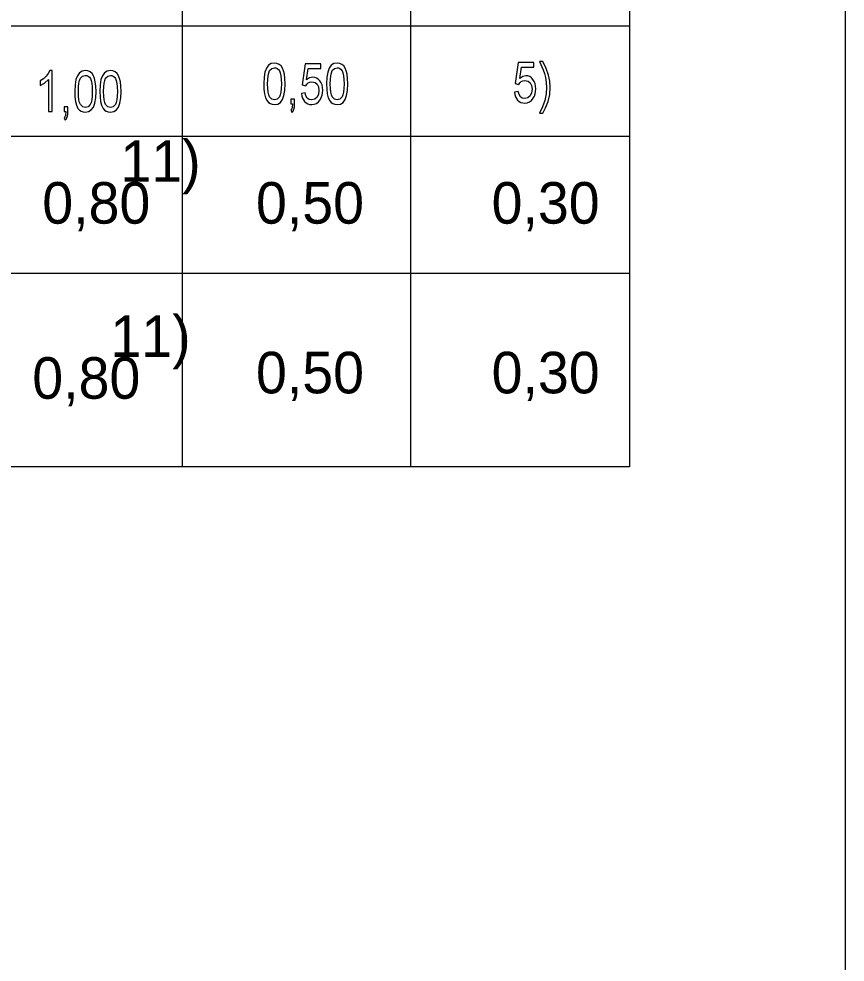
# Model space of a CAD drawing. Extents: x -480568.5 to -480543.1, y -1126945.4 to -1126930.6.
# Drawn here: x -480545.02 to -480543.093, y -1126940.968 to -1126938.768 of the extents above; entities that cross this region are included whole.
import ezdxf

# ---------------------------------------------------------------- set-up
doc = ezdxf.new("R2010")
doc.units = 0
doc.layers.add('detaily', color=7, linetype='Continuous')
doc.layers.add('EL1', color=7, linetype='Continuous')

msp = doc.modelspace()

# ---------------------------------------------------------------- linework, layer by layer
at = {"layer": 'detaily'}
msp.add_line((-480543.0929, -1126930.5663), (-480543.0929, -1126945.4163), dxfattribs=at)
msp.add_lwpolyline([(-480543.5956, -1126939.8124), (-480551.8459, -1126939.8124), (-480551.8459, -1126936.5789), (-480543.5956, -1126936.5789)], close=True, dxfattribs=at)
at = {"layer": 'EL1'}
for p, q in [((-480544.6383, -1126939.8121), (-480544.6383, -1126936.5789)), ((-480544.1063, -1126936.5789), (-480544.1063, -1126939.8121)), ((-480550.8351, -1126938.7844), (-480543.5956, -1126938.7844)), ((-480543.5956, -1126939.0426), (-480551.8459, -1126939.0426)), ((-480543.5956, -1126939.3618), (-480551.8459, -1126939.3618))]:
    msp.add_line(p, q, dxfattribs=at)
for points in [[(-480544.4489, -1126938.9195), (-480544.4484, -1126938.932), (-480544.447, -1126938.9427), (-480544.4446, -1126938.9518), (-480544.4413, -1126938.959), (-480544.4379, -1126938.9629), (-480544.4339, -1126938.9657), (-480544.4292, -1126938.9673), (-480544.424, -1126938.9679), (-480544.4164, -1126938.9666), (-480544.4102, -1126938.9628), (-480544.4054, -1126938.9563), (-480544.4019, -1126938.9469), (-480544.3999, -1126938.9347), (-480544.3992, -1126938.9195), (-480544.3996, -1126938.9069), (-480544.4009, -1126938.8971), (-480544.4028, -1126938.8894), (-480544.4052, -1126938.883), (-480544.4085, -1126938.8779), (-480544.4129, -1126938.8742), (-480544.4182, -1126938.8718), (-480544.424, -1126938.8711), (-480544.4316, -1126938.8724), (-480544.4378, -1126938.8762), (-480544.4426, -1126938.8827), (-480544.4461, -1126938.892), (-480544.4482, -1126938.9042)], [(-480544.3611, -1126938.9423), (-480544.3603, -1126938.9479), (-480544.3588, -1126938.9528), (-480544.3566, -1126938.9571), (-480544.3537, -1126938.9609), (-480544.3503, -1126938.964), (-480544.3463, -1126938.9661), (-480544.3419, -1126938.9675), (-480544.337, -1126938.9679), (-480544.3311, -1126938.9672), (-480544.3259, -1126938.965), (-480544.3213, -1126938.9615), (-480544.3173, -1126938.9565), (-480544.3148, -1126938.9516), (-480544.3129, -1126938.9463), (-480544.3118, -1126938.9406), (-480544.3114, -1126938.9344), (-480544.3118, -1126938.9281), (-480544.3131, -1126938.9222), (-480544.3152, -1126938.9171), (-480544.3182, -1126938.9125), (-480544.3218, -1126938.9088), (-480544.3257, -1126938.9061), (-480544.33, -1126938.9045), (-480544.3347, -1126938.904), (-480544.342, -1126938.9055), (-480544.3489, -1126938.9103), (-480544.3451, -1126938.8839), (-480544.3158, -1126938.8839), (-480544.3158, -1126938.8729), (-480544.3523, -1126938.8729), (-480544.3596, -1126938.9222), (-480544.3509, -1126938.924), (-480544.3485, -1126938.9204), (-480544.3454, -1126938.9175), (-480544.3416, -1126938.9156), (-480544.3367, -1126938.9149), (-480544.3294, -1126938.9163), (-480544.3242, -1126938.9203), (-480544.3212, -1126938.9268), (-480544.3202, -1126938.9351), (-480544.3213, -1126938.944), (-480544.3245, -1126938.951), (-480544.3298, -1126938.9555), (-480544.337, -1126938.9569), (-480544.3429, -1126938.9559), (-480544.3474, -1126938.9528), (-480544.3505, -1126938.9477), (-480544.3523, -1126938.9405)], [(-480544.3026, -1126938.9195), (-480544.3021, -1126938.932), (-480544.3007, -1126938.9427), (-480544.2984, -1126938.9518), (-480544.295, -1126938.959), (-480544.2916, -1126938.9629), (-480544.2876, -1126938.9657), (-480544.283, -1126938.9673), (-480544.2777, -1126938.9679), (-480544.2701, -1126938.9666), (-480544.2639, -1126938.9628), (-480544.2591, -1126938.9563), (-480544.2557, -1126938.9469), (-480544.2536, -1126938.9347), (-480544.2529, -1126938.9195), (-480544.2533, -1126938.9069), (-480544.2546, -1126938.8971), (-480544.2566, -1126938.8894), (-480544.259, -1126938.883), (-480544.2622, -1126938.8779), (-480544.2666, -1126938.8742), (-480544.2719, -1126938.8718), (-480544.2777, -1126938.8711), (-480544.2853, -1126938.8724), (-480544.2915, -1126938.8762), (-480544.2963, -1126938.8827), (-480544.2998, -1126938.892), (-480544.3019, -1126938.9042)], [(-480543.8641, -1126938.939), (-480543.8633, -1126938.9446), (-480543.8619, -1126938.9495), (-480543.8597, -1126938.9539), (-480543.8568, -1126938.9576), (-480543.8533, -1126938.9607), (-480543.8494, -1126938.9629), (-480543.845, -1126938.9642), (-480543.8401, -1126938.9646), (-480543.8342, -1126938.9639), (-480543.8289, -1126938.9618), (-480543.8243, -1126938.9582), (-480543.8204, -1126938.9532), (-480543.8178, -1126938.9483), (-480543.8159, -1126938.943), (-480543.8148, -1126938.9373), (-480543.8144, -1126938.9311), (-480543.8149, -1126938.9248), (-480543.8161, -1126938.919), (-480543.8183, -1126938.9138), (-480543.8212, -1126938.9092), (-480543.8248, -1126938.9055), (-480543.8287, -1126938.9028), (-480543.8331, -1126938.9012), (-480543.8378, -1126938.9007), (-480543.845, -1126938.9023), (-480543.8519, -1126938.907), (-480543.8481, -1126938.8806), (-480543.8188, -1126938.8806), (-480543.8188, -1126938.8696), (-480543.8554, -1126938.8696), (-480543.8627, -1126938.9189), (-480543.8539, -1126938.9208), (-480543.8515, -1126938.9171), (-480543.8485, -1126938.9142), (-480543.8446, -1126938.9123), (-480543.8398, -1126938.9116), (-480543.8324, -1126938.913), (-480543.8273, -1126938.9171), (-480543.8242, -1126938.9235), (-480543.8232, -1126938.9318), (-480543.8243, -1126938.9407), (-480543.8276, -1126938.9477), (-480543.8329, -1126938.9522), (-480543.84, -1126938.9537), (-480543.846, -1126938.9526), (-480543.8504, -1126938.9495), (-480543.8536, -1126938.9444), (-480543.8554, -1126938.9372)], [(-480543.7983, -1126938.9883), (-480543.7915, -1126938.9756), (-480543.7859, -1126938.9608), (-480543.782, -1126938.9447), (-480543.7808, -1126938.928), (-480543.7817, -1126938.9134), (-480543.7846, -1126938.8994), (-480543.7902, -1126938.8836), (-480543.7983, -1126938.8678), (-480543.8056, -1126938.8678), (-480543.797, -1126938.8866), (-480543.794, -1126938.8955), (-480543.7918, -1126938.9047), (-480543.7901, -1126938.9163), (-480543.7895, -1126938.9281), (-480543.7905, -1126938.9432), (-480543.7936, -1126938.9582), (-480543.7986, -1126938.9733), (-480543.8056, -1126938.9883)], [(-480544.9426, -1126938.9838), (-480544.9426, -1126938.8888), (-480544.9482, -1126938.8888), (-480544.9515, -1126938.8951), (-480544.9566, -1126938.9015), (-480544.963, -1126938.9075), (-480544.9703, -1126938.9126), (-480544.9703, -1126938.9238), (-480544.9603, -1126938.9178), (-480544.9513, -1126938.9098), (-480544.9513, -1126938.9838)], [(-480544.8899, -1126938.9373), (-480544.8894, -1126938.9498), (-480544.888, -1126938.9605), (-480544.8857, -1126938.9696), (-480544.8824, -1126938.9768), (-480544.879, -1126938.9807), (-480544.8749, -1126938.9835), (-480544.8703, -1126938.9851), (-480544.865, -1126938.9857), (-480544.8574, -1126938.9844), (-480544.8512, -1126938.9805), (-480544.8464, -1126938.974), (-480544.843, -1126938.9647), (-480544.8409, -1126938.9525), (-480544.8402, -1126938.9373), (-480544.8406, -1126938.9246), (-480544.8419, -1126938.9149), (-480544.8439, -1126938.9072), (-480544.8463, -1126938.9008), (-480544.8495, -1126938.8957), (-480544.8539, -1126938.8919), (-480544.8592, -1126938.8896), (-480544.865, -1126938.8888), (-480544.8726, -1126938.8901), (-480544.8788, -1126938.894), (-480544.8837, -1126938.9005), (-480544.8871, -1126938.9098), (-480544.8892, -1126938.922)], [(-480544.8811, -1126938.9373), (-480544.8808, -1126938.9269), (-480544.88, -1126938.9183), (-480544.8785, -1126938.9115), (-480544.8764, -1126938.9064), (-480544.8714, -1126938.9015), (-480544.8652, -1126938.8998), (-480544.8617, -1126938.9003), (-480544.8586, -1126938.9017), (-480544.8558, -1126938.904), (-480544.8534, -1126938.9072), (-480544.8515, -1126938.9119), (-480544.8501, -1126938.9185), (-480544.8493, -1126938.9269), (-480544.849, -1126938.9373), (-480544.8493, -1126938.948), (-480544.8501, -1126938.9566), (-480544.8516, -1126938.9632), (-480544.8536, -1126938.9677), (-480544.8588, -1126938.973), (-480544.865, -1126938.9747), (-480544.8713, -1126938.973), (-480544.8765, -1126938.9677), (-480544.8785, -1126938.9632), (-480544.88, -1126938.9566), (-480544.8808, -1126938.948)], [(-480544.8314, -1126938.9373), (-480544.8309, -1126938.9498), (-480544.8295, -1126938.9605), (-480544.8271, -1126938.9696), (-480544.8238, -1126938.9768), (-480544.8204, -1126938.9807), (-480544.8164, -1126938.9835), (-480544.8117, -1126938.9851), (-480544.8065, -1126938.9857), (-480544.7989, -1126938.9844), (-480544.7927, -1126938.9805), (-480544.7879, -1126938.974), (-480544.7844, -1126938.9647), (-480544.7824, -1126938.9525), (-480544.7817, -1126938.9373), (-480544.7821, -1126938.9246), (-480544.7834, -1126938.9149), (-480544.7853, -1126938.9072), (-480544.7877, -1126938.9008), (-480544.791, -1126938.8957), (-480544.7954, -1126938.8919), (-480544.8007, -1126938.8896), (-480544.8065, -1126938.8888), (-480544.8141, -1126938.8901), (-480544.8203, -1126938.894), (-480544.8251, -1126938.9005), (-480544.8286, -1126938.9098), (-480544.8307, -1126938.922)], [(-480544.8226, -1126938.9373), (-480544.8223, -1126938.9269), (-480544.8214, -1126938.9183), (-480544.8199, -1126938.9115), (-480544.8179, -1126938.9064), (-480544.8128, -1126938.9015), (-480544.8066, -1126938.8998), (-480544.8032, -1126938.9003), (-480544.8001, -1126938.9017), (-480544.7973, -1126938.904), (-480544.7949, -1126938.9072), (-480544.793, -1126938.9119), (-480544.7916, -1126938.9185), (-480544.7907, -1126938.9269), (-480544.7904, -1126938.9373), (-480544.7907, -1126938.948), (-480544.7916, -1126938.9566), (-480544.7931, -1126938.9632), (-480544.7951, -1126938.9677), (-480544.8003, -1126938.973), (-480544.8065, -1126938.9747), (-480544.8128, -1126938.973), (-480544.818, -1126938.9677), (-480544.82, -1126938.9632), (-480544.8215, -1126938.9566), (-480544.8223, -1126938.948)], [(-480544.4401, -1126938.9195), (-480544.4398, -1126938.9091), (-480544.4389, -1126938.9005), (-480544.4374, -1126938.8937), (-480544.4354, -1126938.8886), (-480544.4303, -1126938.8837), (-480544.4241, -1126938.882), (-480544.4207, -1126938.8825), (-480544.4176, -1126938.8839), (-480544.4148, -1126938.8862), (-480544.4124, -1126938.8894), (-480544.4105, -1126938.8941), (-480544.4091, -1126938.9007), (-480544.4082, -1126938.9092), (-480544.4079, -1126938.9195), (-480544.4082, -1126938.9302), (-480544.4091, -1126938.9388), (-480544.4106, -1126938.9454), (-480544.4126, -1126938.9499), (-480544.4178, -1126938.9552), (-480544.424, -1126938.9569), (-480544.4303, -1126938.9552), (-480544.4355, -1126938.9499), (-480544.4375, -1126938.9454), (-480544.439, -1126938.9388), (-480544.4398, -1126938.9302)], [(-480544.2938, -1126938.9195), (-480544.2935, -1126938.9091), (-480544.2926, -1126938.9005), (-480544.2912, -1126938.8937), (-480544.2891, -1126938.8886), (-480544.2841, -1126938.8837), (-480544.2778, -1126938.882), (-480544.2744, -1126938.8825), (-480544.2713, -1126938.8839), (-480544.2685, -1126938.8862), (-480544.2661, -1126938.8894), (-480544.2642, -1126938.8941), (-480544.2628, -1126938.9007), (-480544.2619, -1126938.9092), (-480544.2617, -1126938.9195), (-480544.2619, -1126938.9302), (-480544.2628, -1126938.9388), (-480544.2643, -1126938.9454), (-480544.2663, -1126938.9499), (-480544.2715, -1126938.9552), (-480544.2777, -1126938.9569), (-480544.284, -1126938.9552), (-480544.2892, -1126938.9499), (-480544.2912, -1126938.9454), (-480544.2927, -1126938.9388), (-480544.2935, -1126938.9302)], [(-480544.386, -1126938.9661), (-480544.3816, -1126938.9661), (-480544.3827, -1126938.9757), (-480544.3841, -1126938.9786), (-480544.386, -1126938.9807), (-480544.383, -1126938.9862), (-480544.3804, -1126938.983), (-480544.3786, -1126938.9787), (-480544.3775, -1126938.9731), (-480544.3772, -1126938.9661), (-480544.3772, -1126938.9551), (-480544.386, -1126938.9551)], [(-480544.9147, -1126938.9838), (-480544.9104, -1126938.9838), (-480544.9115, -1126938.9934), (-480544.9129, -1126938.9963), (-480544.9147, -1126938.9985), (-480544.9118, -1126939.0039), (-480544.9092, -1126939.0008), (-480544.9074, -1126938.9965), (-480544.9063, -1126938.9909), (-480544.906, -1126938.9838), (-480544.906, -1126938.9729), (-480544.9147, -1126938.9729)]]:
    msp.add_lwpolyline(points, close=True, dxfattribs=at)

# ---------------------------------------------------------------- texts
for s, height, rotation, p in [('11)                  ', 0.096829, 360, (-480544.7833, -1126939.148)), ('0,80', 0.09683, 360, (-480544.9656, -1126939.2455)), ('0,50', 0.09683, 360, (-480544.4671, -1126939.2455)), ('0,30', 0.09683, 0, (-480543.9175, -1126939.2455)), ('11)                  ', 0.096829, 360, (-480544.8067, -1126939.5564)), ('0,80', 0.09683, 360, (-480544.9889, -1126939.6538)), ('0,50', 0.09683, 0, (-480544.4671, -1126939.6412)), ('0,30', 0.09683, 0, (-480543.9175, -1126939.6412))]:
    msp.add_text(s, height=height, rotation=rotation, dxfattribs=at).set_placement(p)

doc.saveas('drawing.dxf')
